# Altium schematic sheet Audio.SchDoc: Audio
size A4; DocumentNumber: MB1167; Revision: B.1; SheetNumber: 5; SheetTotal: 17; Project: STM327x6G-EVAL
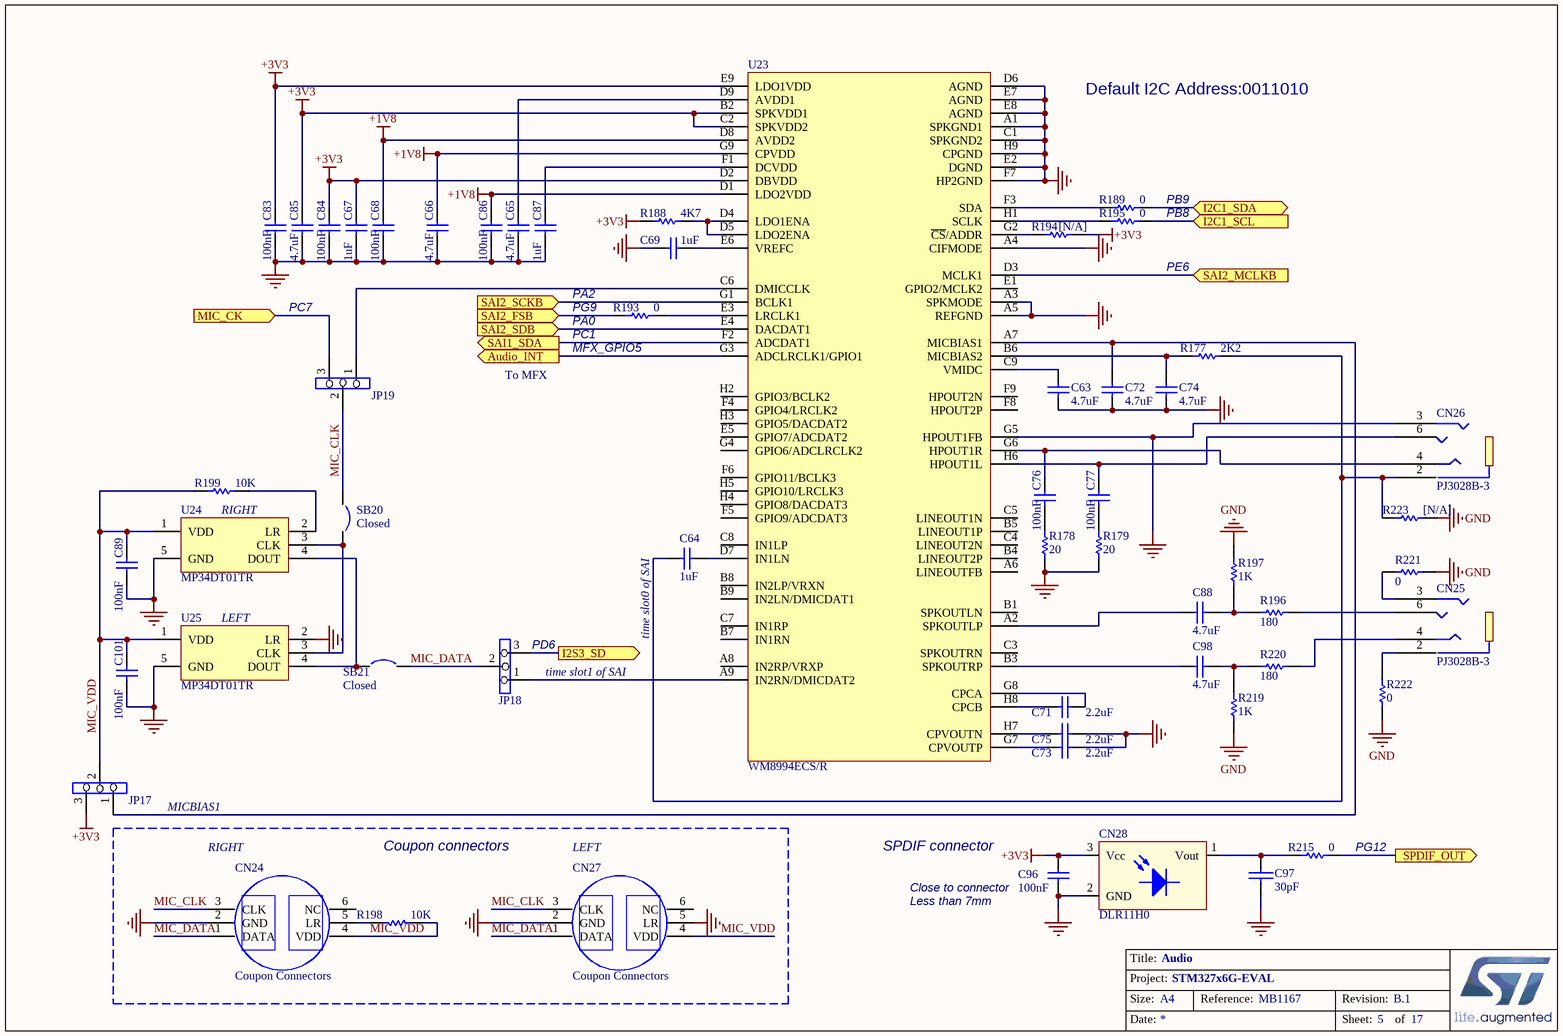
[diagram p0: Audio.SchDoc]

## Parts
C63  4.7uF  [0603C]
C64  1uF  [0603C]
C65  4.7uF  [0603C]
C66  4.7uF  [0603C]
C67  1uF  [0603C]
C68  100nF  [0603C]
C69  1uF  [0603C]
C71  2.2uF  [0603C]
C72  4.7uF  [0603C]
C73  2.2uF  [0603C]
C74  4.7uF  [0603C]
C75  2.2uF  [0603C]
C76  100nF  [0603C]
C77  100nF  [0603C]
C83  100nF  [0603C]
C84  100nF  [0603C]
C85  4.7uF  [0603C]
C86  100nF  [0603C]
C87  1uF  [0603C]
C88  4.7uF  [0603C]
C89  100nF  [0603C]
C96  100nF  [0603C]
C97  30pF  [0603C]
C98  4.7uF  [0603C]
C101  100nF  [0603C]
CN24  Coupon Connectors  [Coupon]
CN25  PJ3028B-3  [PJ3028B]
CN26  PJ3028B-3  [PJ3028B]
CN27  Coupon Connectors  [Coupon]
CN28  DLR11H0  [CONN_DLR11H0]
JP17  (no value)  [SIP3]
JP18  (no value)  [SIP3]
JP19  (no value)  [SIP3]
R177  2K2  [0603R]
R178  20  [0603R]
R179  20  [0603R]
R188  4K7  [0603R]
R189  0  [0603R]
R193  0  [0603R]
R194  [N/A]  [0603R]
R195  0  [0603R]
R196  180  [0402R]
R197  1K  [0402R]
R198  10K  [0603R]
R199  10K  [0603R]
R215  0  [0603R]
R219  1K  [0402R]
R220  180  [0402R]
R221  0  [0603R]
R222  0  [0603R]
R223  [N/A]  [0603R]
SB20  Closed  [SB_0603]
SB21  Closed  [SB_0603]
U23  WM8994ECS/R  [BGA72_0R5_4R5X4]
U24  MP34DT01TR  [MP34DT01TR]
U25  MP34DT01TR  [MP34DT01TR]

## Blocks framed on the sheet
Coupon connectors: CN24 CN27 R198

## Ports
Audio_INT (out), I2C1_SCL (in), I2C1_SDA (bidir), I2S3_SD (out), MIC_CK (in), SAI1_SDA (out), SAI2_FSB (in), SAI2_MCLKB (in), SAI2_SCKB (in), SAI2_SDB (in), SPDIF_OUT (out)

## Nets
+1V8: C66.1 C68.1 C86.1 U23.D1(LDO2VDD) U23.D8(AVDD2) U23.G9(CPVDD)
+3V3: C67.1 C83.1 C84.1 C85.1 C96.2 CN28.3(Vcc) JP17.3 R188.2 R194.1 U23.B2(SPKVDD1) U23.C2(SPKVDD2) U23.D2(DBVDD) U23.E9(LDO1VDD)
GND: C63.1 C65.2 C66.2 C67.2 C68.2 C69.2 C72.1 C73.2 C74.1 C75.2 C83.2 C84.2 C85.2 C86.2 C87.2 C89.2 C96.1 C97.2 C101.2 CN24.2(GND) CN26.3 CN27.2(GND) CN27.5(LR) CN28.2(GND) R178.2 R179.2 R197.2 R219.1 R221.2 R222.2 R223.1 U23.A1(SPKGND1) U23.A3(SPKMODE) U23.A4(CIFMODE) U23.A5(REFGND) U23.C1(SPKGND2) U23.D6(AGND) U23.E2(DGND) U23.E7(AGND) U23.E8(AGND) U23.F7(HP2GND) U23.G5(HPOUT1FB) U23.H9(CPGND) U24.5(GND) U25.2(LR) U25.5(GND)
Audio_INT: U23.G3(ADCLRCLK1/GPIO1) ; port Audio_INT
I2C1_SCL: R195.1 ; port I2C1_SCL
I2C1_SDA: R189.1 ; port I2C1_SDA
I2S3_SD: JP18.3 ; port I2S3_SD
MIC_CK: JP19.3 ; port MIC_CK
MIC_CLK: CN24.3(CLK) CN27.3(CLK) JP19.2 SB20.1
MIC_DATA: CN24.1(DATA) CN27.1(DATA) JP18.2 SB21.2
MIC_VDD: C89.1 C101.1 CN24.4(VDD) CN27.4(VDD) JP17.2 R198.2 R199.2 U24.1(VDD) U25.1(VDD)
SAI1_SDA: U23.F2(ADCDAT1) ; port SAI1_SDA
SAI2_FSB: R193.2 ; port SAI2_FSB
SAI2_MCLKB: U23.D3(MCLK1) ; port SAI2_MCLKB
SAI2_SCKB: U23.G1(BCLK1) ; port SAI2_SCKB
SAI2_SDB: U23.E4(DACDAT1) ; port SAI2_SDB
SPDIF_OUT: R215.1 ; port SPDIF_OUT
NetC63_2: C63.2 U23.C9(VMIDC)
NetC64_1: C64.1 U23.D7(IN1LN)
NetC64_2: C64.2 CN26.2 R177.1 R223.2
NetC65_1: C65.1 U23.D9(AVDD1)
NetC69_1: C69.1 U23.E6(VREFC)
NetC71_1: C71.1 U23.H8(CPCB)
NetC71_2: C71.2 U23.G8(CPCA)
NetC72_2: C72.2 JP17.1 U23.A7(MICBIAS1)
NetC73_1: C73.1 U23.G7(CPVOUTP)
NetC74_2: C74.2 R177.2 U23.B6(MICBIAS2)
NetC75_1: C75.1 U23.H7(CPVOUTN)
NetC76_1: C76.1 CN26.4 U23.G6(HPOUT1R)
NetC76_2: C76.2 R178.1
NetC77_1: C77.1 CN26.6 U23.H6(HPOUT1L)
NetC77_2: C77.2 R179.1
NetC87_1: C87.1 U23.F1(DCVDD)
NetC88_1: C88.1 R196.1 R197.1
NetC88_2: C88.2 U23.A2(SPKOUTLP)
NetC97_1: C97.1 CN28.1(Vout) R215.2
NetC98_1: C98.1 R219.2 R220.2
NetC98_2: C98.2 U23.B3(SPKOUTRP)
NetCN24_5: CN24.5(LR) R198.1
NetCN25_2: CN25.2 R222.1
NetCN25_3: CN25.3 R221.1
NetCN25_4: CN25.4 R220.1
NetCN25_6: CN25.6 R196.2
NetJP18_1: JP18.1 U23.A9(IN2RN/DMICDAT2)
NetJP19_1: JP19.1 U23.C6(DMICCLK)
NetR188_1: R188.1 U23.D4(LDO1ENA) U23.D5(LDO2ENA)
NetR189_2: R189.2 U23.F3(SDA)
NetR193_1: R193.1 U23.E3(LRCLK1)
NetR194_2: R194.2 U23.G2(~{CS}/ADDR)
NetR195_2: R195.2 U23.H1(SCLK)
NetR199_1: R199.1 U24.2(LR)
NetSB20_2: SB20.2 U24.3(CLK) U25.3(CLK)
NetSB21_1: SB21.1 U24.4(DOUT) U25.4(DOUT)

Not connected (* = marked no-connect by the designer): CN24 6(NC); CN27 6(NC); U23 A6(LINEOUTFB) A8(IN2RP/VRXP) B1(SPKOUTLN) B4(LINEOUT2P) B5(LINEOUT1P) B7(IN1RN) B8(IN2LP/VRXN) B9(IN2LN/DMICDAT1) C3(SPKOUTRN) C4(LINEOUT2N) C5(LINEOUT1N) C7(IN1RP) C8(IN1LP) E1(GPIO2/MCLK2) E5(GPIO7/ADCDAT2) F4(GPIO4/LRCLK2) F5(GPIO9/ADCDAT3) F6(GPIO11/BCLK3) F8(HPOUT2P) F9(HPOUT2N) G4(GPIO6/ADCLRCLK2) H2(GPIO3/BCLK2) H3(GPIO5/DACDAT2) H4(GPIO8/DACDAT3) H5(GPIO10/LRCLK3)

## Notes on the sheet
- Default I2C Address:0011010
- PB9
- PB8
- PC7
- PA2
- (near R193) PG9
- PE6
- To MFX
- (near R193) PA0
- (near R193) PC1
- (near R193) MFX_GPIO5
- RIGHT
- (near U25) LEFT
- (near JP18) PD6
- (near C64) time slot0 of SAI
- (near JP18) time slot1 of SAI
- MICBIAS1
- LEFT
- SPDIF connector
- (near R215) PG12
- (near C96) Close to connector
- Less than 7mm

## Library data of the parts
C63 C65 C66 C68 C72 C74 C76 C77 C83-C86 C89 C96 C101 = Cap: Capacitor; Value: 10nF
C64 C67 C69 C71 C73 C75 C87 = CAP: Capacitor; Value: 100nF
C88 C98 = Cap: Capacitor; Value: 10nF; Ordered by: Subcon
C97 = CAP: Capacitor
CN24 CN27 = Coupon Connectors: Header, 3-Pin, Single row
CN28 = OPTO
JP17-JP19 = Jumper3
R177-R179 R188 R189 R193-R195 R198 R199 R215 R223 = Res1: Resistor; Value: 1K
R196 R220-R222 = Res1: Resistor; Value: 1K; Ordered by: Subcon
R197 R219 = Res1: Resistor; Ordered by: Subcon
SB20 SB21 = Circuit Breaker_close: Circuit Breaker
U24 U25 = MP34DT01TR: MEMS audio sensor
